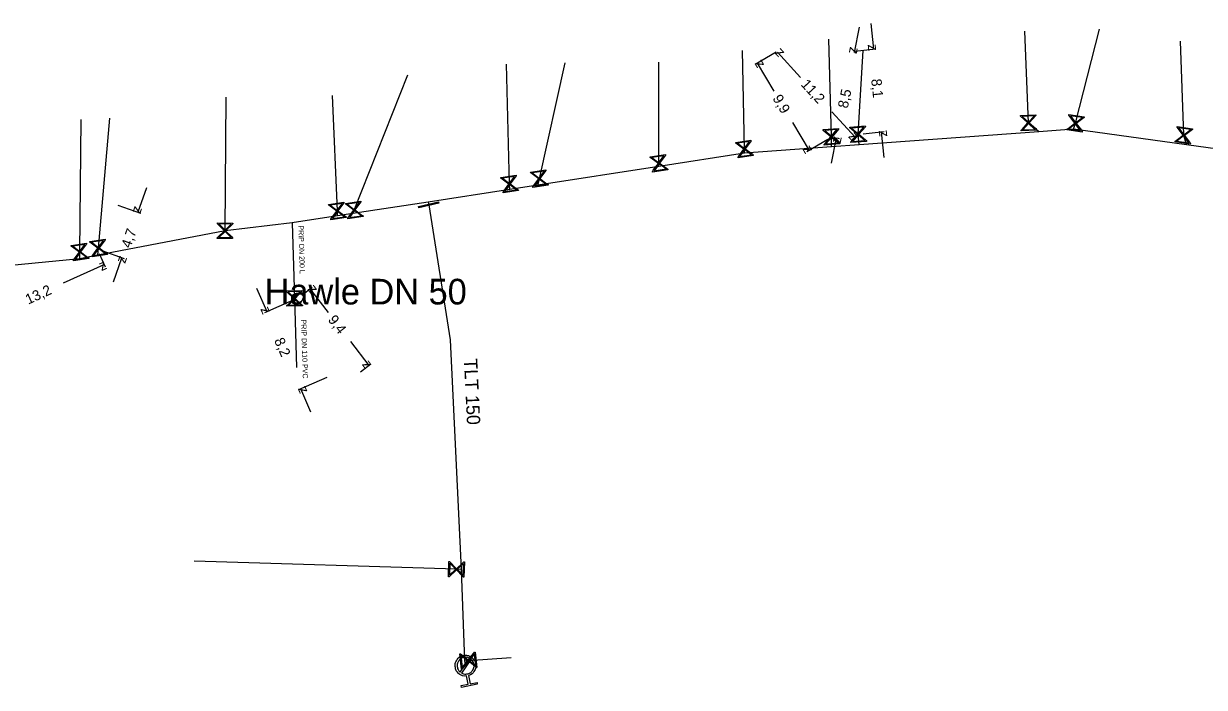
# Model space of a CAD drawing. Extents: x -643544 to -637295, y -1119190 to -1111715.
# Drawn here: x -641787.1 to -641672.1, y -1115263.7 to -1115199 of the extents above; entities that cross this region are included whole.
import ezdxf

# ---------------------------------------------------------------- set-up
doc = ezdxf.new("R2010")
doc.units = 0
for name, color, linetype in [('Default', 7, 'Continuous'), ('VP Hydrant', 7, 'Continuous'), ('VP Kótování', 7, 'Continuous'), ('VP Popis nerozlišený', 7, 'Continuous'), ('VP Popis přípojky', 7, 'Continuous'), ('VP Přípojka', 7, 'Continuous'), ('VP Řad', 7, 'Continuous'), ('VP Řad - popis', 7, 'Continuous'), ('VP Šoupě', 7, 'Continuous')]:
    doc.layers.add(name, color=color, linetype=linetype)

msp = doc.modelspace()

# ---------------------------------------------------------------- linework, layer by layer
at = {"layer": 'Default'}
for points in [[(-641743.99, -1115262.54), (-641744.35, -1115262.58), (-641744.65, -1115262.37), (-641744.99, -1115262.14), (-641745.07, -1115261.73), (-641745.15, -1115261.32), (-641744.92, -1115260.98), (-641744.69, -1115260.64), (-641744.28, -1115260.56), (-641743.88, -1115260.48), (-641743.53, -1115260.71), (-641743.19, -1115260.94), (-641743.11, -1115261.35), (-641743.03, -1115261.75), (-641743.26, -1115262.1), (-641743.46, -1115262.4), (-641743.81, -1115262.5)], [(-641743.71, -1115260.82), (-641743.96, -1115260.69), (-641744.24, -1115260.74), (-641744.57, -1115260.81), (-641744.76, -1115261.09), (-641744.95, -1115261.37), (-641744.89, -1115261.7), (-641744.83, -1115261.98), (-641744.62, -1115262.16)], [(-641744.47, -1115262.26), (-641744.22, -1115262.4), (-641743.93, -1115262.34), (-641743.6, -1115262.27), (-641743.41, -1115262), (-641743.23, -1115261.72), (-641743.29, -1115261.39), (-641743.35, -1115261.1), (-641743.56, -1115260.92)]]:
    msp.add_open_spline(points, degree=3, dxfattribs=at)
at = {"layer": 'VP Hydrant'}
for points in [[(-641744.62, -1115262.16), (-641743.71, -1115260.82)], [(-641743.56, -1115260.92), (-641744.47, -1115262.26)], [(-641743.81, -1115262.5), (-641743.65, -1115263.31), (-641742.97, -1115263.17), (-641742.94, -1115263.35), (-641744.47, -1115263.65), (-641744.51, -1115263.47), (-641743.83, -1115263.34), (-641743.99, -1115262.54)]]:
    msp.add_lwpolyline(points, dxfattribs=at)
at = {"layer": 'VP Kótování'}
for points in [[(-641705.74, -1115199.35), (-641706.24, -1115201.79)], [(-641704.62, -1115198.99), (-641704.37, -1115201.48)], [(-641713.85, -1115201.76), (-641715.88, -1115202.96)], [(-641713.79, -1115201.85), (-641713.9, -1115201.95)], [(-641711.46, -1115204.25), (-641713.72, -1115201.78)], [(-641706.18, -1115201.81), (-641706, -1115201.84)], [(-641706.17, -1115201.66), (-641704.12, -1115201.45)], [(-641714.04, -1115205.57), (-641715.66, -1115202.84)], [(-641708.41, -1115207.57), (-641706.15, -1115210.04)], [(-641712.24, -1115208.62), (-641710.62, -1115211.36)], [(-641708.46, -1115212.57), (-641707.96, -1115210.12)], [(-641707.89, -1115210.13), (-641707.71, -1115210.17)], [(-641706.22, -1115210.1), (-641706.33, -1115210.21)], [(-641705.35, -1115209.72), (-641703.31, -1115209.51)], [(-641703.31, -1115212.02), (-641703.56, -1115209.53)], [(-641708.81, -1115210.29), (-641710.84, -1115211.48)], [(-641775.16, -1115214.99), (-641775.99, -1115217.35)], [(-641777.95, -1115216.67), (-641775.76, -1115217.44)], [(-641779.77, -1115221.39), (-641779.18, -1115222.68)], [(-641779.51, -1115221.1), (-641777.32, -1115221.87)], [(-641783.24, -1115224.25), (-641779.29, -1115222.45)], [(-641778.38, -1115224.15), (-641777.55, -1115221.79)], [(-641764.44, -1115224.76), (-641763.43, -1115227.05)], [(-641760.03, -1115225.43), (-641759.02, -1115224.66)], [(-641757.44, -1115227.14), (-641759.22, -1115224.81)], [(-641760.89, -1115225.94), (-641763.66, -1115227.15)], [(-641755.3, -1115229.96), (-641753.52, -1115232.29)], [(-641754.33, -1115232.91), (-641753.32, -1115232.14)], [(-641757.6, -1115233.45), (-641760.37, -1115234.66)], [(-641759.14, -1115236.85), (-641760.14, -1115234.56)]]:
    msp.add_lwpolyline(points, dxfattribs=at)
at = {"layer": 'VP Přípojka'}
for points in [[(-641688.25, -1115209.52), (-641689.25, -1115208.66), (-641689.62, -1115199.74)], [(-641684.88, -1115209.28), (-641684.68, -1115208.7), (-641682.36, -1115199.53)], [(-641708.43, -1115211), (-641708.45, -1115210.02), (-641708.72, -1115200.51)], [(-641673.87, -1115210.8), (-641674.14, -1115209.87), (-641674.46, -1115200.71)], [(-641716.91, -1115211.62), (-641716.92, -1115211.2), (-641717.12, -1115201.6)], [(-641705.74, -1115210.81), (-641705.85, -1115209.77), (-641705.35, -1115201.62)], [(-641739.79, -1115215.15), (-641739.8, -1115214.62), (-641740.09, -1115202.93)], [(-641737.04, -1115214.73), (-641736.9, -1115214.1), (-641734.4, -1115202.81)], [(-641725.25, -1115212.92), (-641725.25, -1115212.6), (-641725.25, -1115202.74)], [(-641755.06, -1115217.5), (-641754.92, -1115217.15), (-641749.7, -1115203.99)], [(-641767.51, -1115219.17), (-641767.39, -1115206.15)], [(-641756.55, -1115217.73), (-641756.57, -1115217.24), (-641757.03, -1115206)], [(-641781.65, -1115221.9), (-641781.64, -1115221.24), (-641781.53, -1115208.32)], [(-641779.89, -1115221.56), (-641779.83, -1115220.85), (-641778.73, -1115208.19)], [(-641760.96, -1115218.41), (-641760.75, -1115225.76)], [(-641760.75, -1115225.76), (-641760.56, -1115232.5)], [(-641744.5, -1115252.16), (-641744.97, -1115252.15), (-641770.52, -1115251.35)], [(-641744.18, -1115261.08), (-641743.81, -1115261.04), (-641739.64, -1115260.75)], [(-641744.18, -1115261.08), (-641744.09, -1115261.54)]]:
    msp.add_lwpolyline(points, dxfattribs=at)
at = {"layer": 'VP Řad'}
for points in [[(-641640.66, -1115215.41), (-641644.56, -1115214.85), (-641656.02, -1115213.27), (-641661.42, -1115212.52), (-641661.84, -1115212.45), (-641662.99, -1115212.3), (-641666.11, -1115211.87), (-641673.87, -1115210.8), (-641684.88, -1115209.28), (-641688.25, -1115209.52), (-641705.74, -1115210.81), (-641708.43, -1115211), (-641716.91, -1115211.62), (-641725.25, -1115212.92), (-641737.04, -1115214.73), (-641739.79, -1115215.15), (-641747.73, -1115216.38), (-641755.06, -1115217.5), (-641756.55, -1115217.73), (-641760.96, -1115218.41), (-641767.51, -1115219.17), (-641779.89, -1115221.56), (-641781.65, -1115221.9), (-641793.05, -1115223.02)], [(-641747.73, -1115216.38), (-641747.67, -1115216.64), (-641745.57, -1115229.81), (-641744.5, -1115252.16), (-641744.18, -1115261.08)]]:
    msp.add_lwpolyline(points, dxfattribs=at)
at = {"layer": 'VP Šoupě'}
for points in [[(-641688.46, -1115209.37), (-641689.96, -1115209.44), (-641689.97, -1115209.38), (-641689.88, -1115209.29), (-641689.31, -1115208.66), (-641690.03, -1115208.01), (-641690.03, -1115207.94), (-641688.53, -1115207.88), (-641688.53, -1115207.94), (-641689.19, -1115208.66), (-641688.56, -1115209.22), (-641688.47, -1115209.31), (-641688.46, -1115209.37)], [(-641684.04, -1115209.55), (-641685.53, -1115209.34), (-641685.52, -1115209.28), (-641685.41, -1115209.2), (-641684.74, -1115208.69), (-641685.33, -1115207.92), (-641685.32, -1115207.85), (-641683.83, -1115208.06), (-641683.84, -1115208.13), (-641684.62, -1115208.71), (-641684.11, -1115209.38), (-641684.03, -1115209.48), (-641684.04, -1115209.55)], [(-641705.05, -1115210.46), (-641706.55, -1115210.57), (-641706.55, -1115210.5), (-641706.46, -1115210.41), (-641705.91, -1115209.77), (-641706.65, -1115209.14), (-641706.65, -1115209.07), (-641705.16, -1115208.96), (-641705.15, -1115209.03), (-641705.79, -1115209.76), (-641705.15, -1115210.31), (-641705.05, -1115210.39), (-641705.05, -1115210.46)], [(-641689.88, -1115208.03), (-641689.25, -1115208.6), (-641688.69, -1115207.98), (-641689.88, -1115208.03)], [(-641688.63, -1115209.29), (-641689.25, -1115208.72), (-641689.81, -1115209.34), (-641688.63, -1115209.29)], [(-641684.18, -1115209.43), (-641684.69, -1115208.76), (-641685.36, -1115209.27), (-641684.18, -1115209.43)], [(-641685.18, -1115207.97), (-641684.67, -1115208.64), (-641684, -1115208.13), (-641685.18, -1115207.97)], [(-641673.5, -1115210.72), (-641674.99, -1115210.51), (-641674.98, -1115210.45), (-641674.87, -1115210.37), (-641674.2, -1115209.86), (-641674.79, -1115209.09), (-641674.78, -1115209.02), (-641673.29, -1115209.23), (-641673.3, -1115209.3), (-641674.08, -1115209.88), (-641673.57, -1115210.55), (-641673.49, -1115210.65), (-641673.5, -1115210.72)], [(-641707.65, -1115210.71), (-641709.15, -1115210.82), (-641709.15, -1115210.75), (-641709.07, -1115210.66), (-641708.52, -1115210.02), (-641709.25, -1115209.39), (-641709.26, -1115209.32), (-641707.76, -1115209.21), (-641707.76, -1115209.28), (-641708.39, -1115210.01), (-641707.76, -1115210.56), (-641707.66, -1115210.64), (-641707.65, -1115210.71)], [(-641709.1, -1115209.41), (-641708.46, -1115209.96), (-641707.91, -1115209.32), (-641709.1, -1115209.41)], [(-641707.82, -1115210.63), (-641708.45, -1115210.08), (-641709, -1115210.71), (-641707.82, -1115210.63)], [(-641706.5, -1115209.16), (-641705.86, -1115209.71), (-641705.31, -1115209.07), (-641706.5, -1115209.16)], [(-641705.21, -1115210.38), (-641705.85, -1115209.83), (-641706.39, -1115210.46), (-641705.21, -1115210.38)], [(-641673.64, -1115210.6), (-641674.15, -1115209.93), (-641674.82, -1115210.44), (-641673.64, -1115210.6)], [(-641674.64, -1115209.14), (-641674.13, -1115209.81), (-641673.46, -1115209.3), (-641674.64, -1115209.14)], [(-641716.06, -1115211.83), (-641717.55, -1115212.05), (-641717.56, -1115211.99), (-641717.48, -1115211.89), (-641716.98, -1115211.21), (-641717.76, -1115210.64), (-641717.77, -1115210.57), (-641716.29, -1115210.34), (-641716.28, -1115210.41), (-641716.86, -1115211.19), (-641716.18, -1115211.69), (-641716.07, -1115211.76), (-641716.06, -1115211.83)], [(-641717.61, -1115210.64), (-641716.93, -1115211.14), (-641716.43, -1115210.46), (-641717.61, -1115210.64)], [(-641716.23, -1115211.76), (-641716.91, -1115211.26), (-641717.4, -1115211.94), (-641716.23, -1115211.76)], [(-641724.39, -1115213.22), (-641725.88, -1115213.45), (-641725.89, -1115213.39), (-641725.81, -1115213.28), (-641725.31, -1115212.61), (-641726.09, -1115212.03), (-641726.1, -1115211.97), (-641724.62, -1115211.74), (-641724.61, -1115211.81), (-641725.19, -1115212.59), (-641724.51, -1115213.08), (-641724.4, -1115213.16), (-641724.39, -1115213.22)], [(-641725.94, -1115212.04), (-641725.26, -1115212.54), (-641724.76, -1115211.86), (-641725.94, -1115212.04)], [(-641736.04, -1115214.73), (-641737.53, -1115214.95), (-641737.54, -1115214.89), (-641737.46, -1115214.79), (-641736.96, -1115214.11), (-641737.74, -1115213.54), (-641737.75, -1115213.47), (-641736.27, -1115213.24), (-641736.26, -1115213.31), (-641736.84, -1115214.09), (-641736.16, -1115214.59), (-641736.05, -1115214.66), (-641736.04, -1115214.73)], [(-641737.59, -1115213.54), (-641736.91, -1115214.04), (-641736.41, -1115213.36), (-641737.59, -1115213.54)], [(-641724.56, -1115213.15), (-641725.24, -1115212.66), (-641725.73, -1115213.33), (-641724.56, -1115213.15)], [(-641738.94, -1115215.25), (-641740.43, -1115215.47), (-641740.44, -1115215.41), (-641740.36, -1115215.31), (-641739.86, -1115214.63), (-641740.64, -1115214.06), (-641740.65, -1115213.99), (-641739.17, -1115213.76), (-641739.16, -1115213.83), (-641739.74, -1115214.61), (-641739.06, -1115215.11), (-641738.95, -1115215.18), (-641738.94, -1115215.25)], [(-641740.49, -1115214.06), (-641739.81, -1115214.56), (-641739.31, -1115213.88), (-641740.49, -1115214.06)], [(-641739.11, -1115215.18), (-641739.79, -1115214.68), (-641740.28, -1115215.36), (-641739.11, -1115215.18)], [(-641736.21, -1115214.66), (-641736.89, -1115214.16), (-641737.38, -1115214.84), (-641736.21, -1115214.66)], [(-641755.71, -1115217.87), (-641757.2, -1115218.09), (-641757.21, -1115218.03), (-641757.13, -1115217.93), (-641756.63, -1115217.25), (-641757.41, -1115216.68), (-641757.42, -1115216.61), (-641755.94, -1115216.38), (-641755.93, -1115216.45), (-641756.51, -1115217.23), (-641755.83, -1115217.73), (-641755.72, -1115217.8), (-641755.71, -1115217.87)], [(-641757.26, -1115216.68), (-641756.58, -1115217.18), (-641756.08, -1115216.5), (-641757.26, -1115216.68)], [(-641754.06, -1115217.78), (-641755.55, -1115218), (-641755.56, -1115217.94), (-641755.48, -1115217.84), (-641754.98, -1115217.16), (-641755.76, -1115216.59), (-641755.77, -1115216.52), (-641754.29, -1115216.29), (-641754.28, -1115216.36), (-641754.86, -1115217.14), (-641754.18, -1115217.64), (-641754.07, -1115217.71), (-641754.06, -1115217.78)], [(-641755.61, -1115216.59), (-641754.93, -1115217.09), (-641754.43, -1115216.41), (-641755.61, -1115216.59)], [(-641746.68, -1115216.48), (-641748.63, -1115216.93), (-641748.66, -1115216.8), (-641746.71, -1115216.35), (-641746.68, -1115216.48)], [(-641755.88, -1115217.8), (-641756.56, -1115217.3), (-641757.05, -1115217.98), (-641755.88, -1115217.8)], [(-641754.23, -1115217.71), (-641754.91, -1115217.21), (-641755.4, -1115217.89), (-641754.23, -1115217.71)], [(-641766.77, -1115219.93), (-641768.27, -1115219.91), (-641768.27, -1115219.85), (-641768.17, -1115219.76), (-641767.57, -1115219.17), (-641768.25, -1115218.48), (-641768.25, -1115218.41), (-641766.75, -1115218.43), (-641766.75, -1115218.49), (-641767.45, -1115219.17), (-641766.86, -1115219.77), (-641766.77, -1115219.86), (-641766.77, -1115219.93)], [(-641766.92, -1115219.83), (-641767.51, -1115219.23), (-641768.11, -1115219.82), (-641766.92, -1115219.83)], [(-641768.1, -1115218.51), (-641767.51, -1115219.11), (-641766.91, -1115218.52), (-641768.1, -1115218.51)], [(-641780.78, -1115221.87), (-641782.27, -1115222.1), (-641782.28, -1115222.03), (-641782.2, -1115221.93), (-641781.7, -1115221.25), (-641782.49, -1115220.68), (-641782.5, -1115220.61), (-641781.01, -1115220.38), (-641781, -1115220.45), (-641781.58, -1115221.23), (-641780.9, -1115221.73), (-641780.79, -1115221.8), (-641780.78, -1115221.87)], [(-641782.33, -1115220.68), (-641781.65, -1115221.18), (-641781.15, -1115220.5), (-641782.33, -1115220.68)], [(-641778.97, -1115221.48), (-641780.46, -1115221.71), (-641780.47, -1115221.64), (-641780.39, -1115221.54), (-641779.89, -1115220.86), (-641780.68, -1115220.29), (-641780.69, -1115220.22), (-641779.2, -1115219.99), (-641779.19, -1115220.06), (-641779.77, -1115220.84), (-641779.09, -1115221.34), (-641778.98, -1115221.41), (-641778.97, -1115221.48)], [(-641780.52, -1115220.29), (-641779.84, -1115220.79), (-641779.34, -1115220.11), (-641780.52, -1115220.29)], [(-641780.95, -1115221.8), (-641781.63, -1115221.3), (-641782.13, -1115221.98), (-641780.95, -1115221.8)], [(-641779.14, -1115221.41), (-641779.82, -1115220.91), (-641780.32, -1115221.59), (-641779.14, -1115221.41)], [(-641759.98, -1115226.49), (-641761.48, -1115226.53), (-641761.48, -1115226.46), (-641761.39, -1115226.37), (-641760.81, -1115225.76), (-641761.52, -1115225.1), (-641761.52, -1115225.03), (-641760.02, -1115224.99), (-641760.02, -1115225.05), (-641760.69, -1115225.76), (-641760.08, -1115226.34), (-641759.98, -1115226.42), (-641759.98, -1115226.49)], [(-641761.37, -1115225.12), (-641760.75, -1115225.7), (-641760.18, -1115225.09), (-641761.37, -1115225.12)], [(-641760.14, -1115226.4), (-641760.75, -1115225.82), (-641761.32, -1115226.43), (-641760.14, -1115226.4)], [(-641744.2, -1115251.42), (-641744.24, -1115252.92), (-641744.3, -1115252.91), (-641744.39, -1115252.82), (-641744.97, -1115252.21), (-641745.67, -1115252.89), (-641745.74, -1115252.88), (-641745.7, -1115251.38), (-641745.64, -1115251.39), (-641744.97, -1115252.09), (-641744.36, -1115251.51), (-641744.27, -1115251.41), (-641744.2, -1115251.42)], [(-641745.64, -1115252.73), (-641745.03, -1115252.15), (-641745.61, -1115251.54), (-641745.64, -1115252.73)], [(-641744.3, -1115251.57), (-641744.91, -1115252.15), (-641744.33, -1115252.76), (-641744.3, -1115251.57)], [(-641743.14, -1115260.21), (-641742.98, -1115261.71), (-641743.05, -1115261.71), (-641743.15, -1115261.63), (-641743.8, -1115261.1), (-641744.41, -1115261.86), (-641744.47, -1115261.87), (-641744.64, -1115260.38), (-641744.57, -1115260.37), (-641743.82, -1115260.98), (-641743.29, -1115260.32), (-641743.21, -1115260.22), (-641743.14, -1115260.21)], [(-641744.4, -1115261.71), (-641743.87, -1115261.05), (-641744.53, -1115260.52), (-641744.4, -1115261.71)], [(-641743.22, -1115260.38), (-641743.75, -1115261.03), (-641743.09, -1115261.56), (-641743.22, -1115260.38)]]:
    msp.add_lwpolyline(points, dxfattribs=at)

# ---------------------------------------------------------------- texts
at = {"layer": 'VP Kótování'}
for s, rotation, p in [('z', 132.5108, (-641713.01, -1115201.81)), ('z', 258.35, (-641706.63, -1115201.2)), ('z', 275.7617, (-641704.92, -1115201.03)), ('z', 120.5937, (-641714.98, -1115203.01)), ('8,1', 275.7617, (-641704.58, -1115204.41)), ('11,2', 312.5108, (-641711.49, -1115204.96)), ('8,5', 78.35, (-641706.87, -1115207.3)), ('9,9', 300.5937, (-641714.22, -1115206.26)), ('z', 78.35, (-641707.57, -1115210.71)), ('z', 312.5108, (-641706.86, -1115210.01)), ('z', 95.7617, (-641703.01, -1115209.98)), ('z', 300.5937, (-641711.31, -1115211.18)), ('z', 250.6204, (-641776.3, -1115216.72)), ('4,7', 70.6204, (-641776.72, -1115220.93)), ('z', 70.6204, (-641777.25, -1115222.42)), ('z', 24.5112, (-641779.54, -1115223.11)), ('13,2', 24.5112, (-641786.68, -1115226.37)), ('z', 127.3419, (-641758.52, -1115224.91)), ('z', 293.6679, (-641764.09, -1115226.79)), ('9,4', 307.3419, (-641757.54, -1115227.85)), ('8,2', 293.6679, (-641762.75, -1115229.85)), ('z', 307.3419, (-641754.22, -1115232.19)), ('z', 113.6679, (-641759.48, -1115234.82))]:
    msp.add_text(s, height=1, rotation=rotation, dxfattribs=at).set_placement(p)
at = {"layer": 'VP Popis nerozlišený'}
msp.add_text('Hawle DN 50', height=2.5, dxfattribs=at).set_placement((-641763.66, -1115226.35))
at = {"layer": 'VP Popis přípojky'}
for s, rotation, p in [('PRIP DN 200 L', 271.6203, (-641760.36, -1115218.65)), ('PRIP DN 110 PVC', 271.6237, (-641760.1, -1115227.82))]:
    msp.add_text(s, height=0.5, rotation=rotation, dxfattribs=at).set_placement(p)
at = {"layer": 'VP Řad - popis'}
msp.add_text('TLT 150', height=1.3, rotation=272.7409, dxfattribs=at).set_placement((-641744.25, -1115231.64))

doc.saveas('drawing.dxf')
